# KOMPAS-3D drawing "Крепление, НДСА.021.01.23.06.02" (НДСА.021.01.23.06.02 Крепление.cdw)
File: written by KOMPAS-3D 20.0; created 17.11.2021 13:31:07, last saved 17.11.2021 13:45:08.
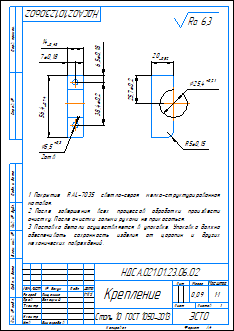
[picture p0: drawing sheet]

Sheet 1: A4, portrait

Document properties: Параметр неуказанной шероховатости: Ra 6,3; Полное имя файла: НДСА.021.01.23.06.02 Крепление.m3d; PLM_CDWXDTO: <item xmlns="http://appius.ru/pdm" xmlns:xs="http://www.w3.org/2001/XMLSchema" xmlns:xsi="http://www.w3.org/2001/XMLSchema-instance" xsi:type="item">  <element xmlns:d2p1="http://v8.1c.ru/8.1/data/enterprise/current-config" xsi:type="d2p1:CatalogRef.aps_Элемен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; Масса: 0.0881412; PDM_DOCXDTO: <item xmlns="http://appius.ru/pdm" xmlns:xs="http://www.w3.org/2001/XMLSchema" xmlns:xsi="http://www.w3.org/2001/XMLSchema-instance" xsi:type="item">  <element xmlns:d2p1="http://v8.1c.ru/8.1/data/enterprise/current-config" xsi:type="d2p1:CatalogRef.aps_Элемен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; PDM_ITEMXDTO: <item xmlns="http://appius.ru/pdm" xmlns:xs="http://www.w3.org/2001/XMLSchema" xmlns:xsi="http://www.w3.org/2001/XMLSchema-instance" xsi:type="item">  <element xmlns:d2p1="http://v8.1c.ru/8.1/data/enterprise/current-config" xsi:type="d2p1:CatalogRef.aps_Элемен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

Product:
- Part/product: Крепление  | designation НДСА.021.01.23.06.02
    Масса: 0.0881412
    additional columns: <item xmlns="http://appius.ru/pdm" xmlns:xs="http://www.w3.org/2001/XMLSchema" x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; <item xmlns="http://appius.ru/pdm" xmlns:xs="http://www.w3.org/2001/XMLSchema" x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
    source file: НДСА.021.01.23.06.02 Крепление.cdw

Title block, sheet 1: Наименование: Крепление; designation: НДСА.021.01.23.06.02; Материал: Сталь 10  ГОСТ 1050-2013; Масса: 0,09; Количество листов документа: 1; organisation: ЭСТО; Форматы листов документа: A4; stored path: C:\Users\s.pischagina\Desktop\PLM\НДСА.021.01.23.06.02 Крепление.cdw; Разработал: Пищагина; Проверил: Белецкий; Утвердил: Виноградов; Разработал, date: 17.11.21

Views: Вид 1, Спереди, Проекционный вид 2
Referenced files in C:\Users\s.pischagina\Desktop\PLM\: НДСА.021.01.23.06.02 Крепление.m3d
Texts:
  Ra 6,3
  НДСА.021.01.23.06.02 Крепление
Dimensions and other numbers on the sheet: 7±0,18; 14; 6,5±0,18; 38,4±0,2; 56,4; 5,5; 2отв; 25,7±0,2; 20; 25,4; 5±0,15; 1:1; 1; 0,09; 17.11.21

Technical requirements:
  Покрытие RAL-7035 светло-серая мелко-структурированная
  матовая.
  После завершения всех процессов обработки произвести
  очистку. После очистки голыми руками не прикасаться.
  Поставка детали осуществляется в упаковке. Упаковка должна
  обеспечивать сохранность изделия от царапин и других
  механических повреждений.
